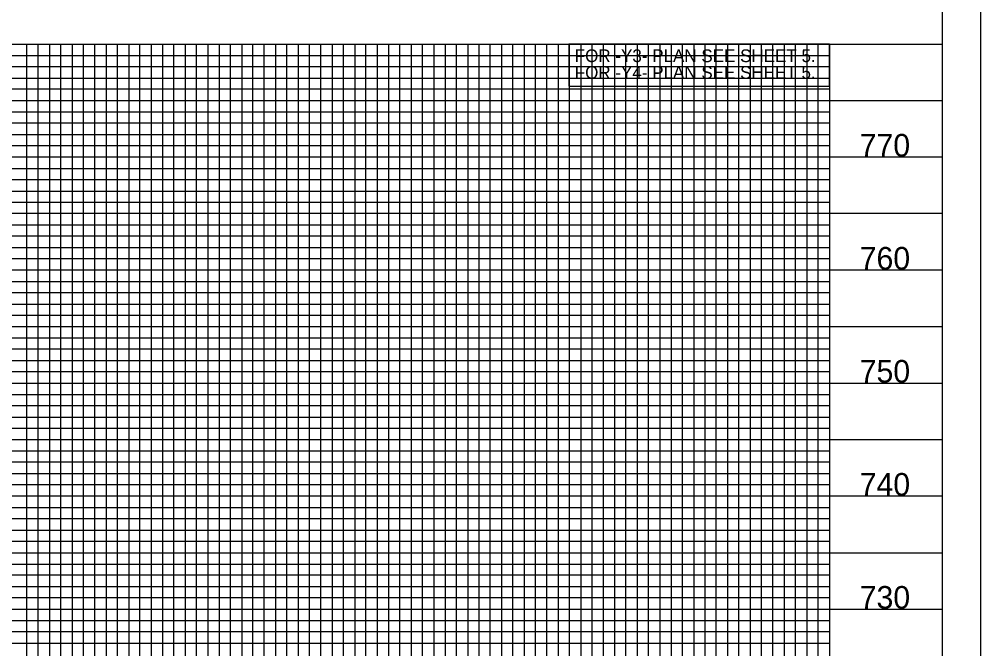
# Model space of a CAD drawing. Extents: x 1524869 to 1526553, y 501099 to 502199.
# Drawn here: x 1526127.7 to 1526553.1, y 501381.1 to 501659.6 of the extents above; entities that cross this region are included whole.
import ezdxf

# ---------------------------------------------------------------- set-up
doc = ezdxf.new("R2010")
doc.units = 0
for name, color, linetype in [('Exist Vertical Profile Vertical Axis Label', 7, 'Continuous'), ('Prop Grid Mask', 7, 'Continuous'), ('Prop Horizontal Alignment Curve and Spiral Data', 7, 'Continuous'), ('Sheet DOT Grid CELL', 7, 'Continuous'), ('Sheet Layout Profile Border Port 2', 7, 'Continuous'), ('Sheet Plot Border Outside CELL', 7, 'Continuous'), ('Sheet Profile CELL', 7, 'Continuous'), ('Sheet Profile Grid Major CELL', 7, 'Continuous'), ('Sheet Profile Grid Middle CELL', 7, 'Continuous'), ('Sheet Profile Grid Minor CELL', 7, 'Continuous')]:
    doc.layers.add(name, color=color, linetype=linetype)

msp = doc.modelspace()

# ---------------------------------------------------------------- linework, layer by layer
at = {"layer": 'Prop Grid Mask'}
msp.add_lwpolyline([(1526370.88, 501629.99), (1526486.08, 501629.99), (1526486.08, 501648.56), (1526370.88, 501648.56)], close=True, dxfattribs=at)
at = {"layer": 'Sheet DOT Grid CELL'}
msp.add_line((1525036.08, 501648.56), (1526535.97, 501648.56), dxfattribs=at)
at = {"layer": 'Sheet Layout Profile Border Port 2'}
msp.add_lwpolyline([(1525086.08, 501648.56), (1526486.08, 501648.56), (1526486.08, 501148.56), (1525086.08, 501148.56)], close=True, dxfattribs=at)
at = {"layer": 'Sheet Plot Border Outside CELL'}
msp.add_lwpolyline([(1524869.08, 501098.56), (1526553.08, 501098.56), (1526553.08, 502198.56), (1524869.08, 502198.56)], close=True, dxfattribs=at)
at = {"layer": 'Sheet Profile CELL'}
msp.add_line((1525036.08, 501648.56), (1526536.08, 501648.56), dxfattribs=at)
msp.add_lwpolyline([(1526536.08, 502173.56), (1525036.08, 502173.56), (1525036.08, 501123.56), (1526536.08, 501123.56)], close=True, dxfattribs=at)
at = {"layer": 'Sheet Profile Grid Major CELL'}
for p, q in [((1526136.08, 501648.56), (1526186.08, 501648.56)), ((1526236.08, 501648.56), (1526286.08, 501648.56)), ((1526336.08, 501648.56), (1526386.08, 501648.56)), ((1526436.08, 501648.56), (1526486.08, 501648.56))]:
    msp.add_line(p, q, dxfattribs=at)
for points in [[(1526086.08, 501148.56), (1526136.08, 501148.56), (1526136.08, 501648.56), (1526186.08, 501648.56), (1526186.08, 501148.56), (1526236.08, 501148.56), (1526236.08, 501648.56), (1526286.08, 501648.56), (1526286.08, 501148.56), (1526336.08, 501148.56), (1526336.08, 501648.56), (1526386.08, 501648.56), (1526386.08, 501148.56), (1526436.08, 501148.56), (1526436.08, 501148.56), (1526436.08, 501648.56), (1526486.08, 501648.56), (1526486.08, 501148.56)], [(1526536.08, 501598.56), (1525036.08, 501598.56)], [(1526536.08, 501548.56), (1525036.08, 501548.56), (1525036.08, 501498.56), (1526536.08, 501498.56)], [(1526536.08, 501448.56), (1525036.08, 501448.56), (1525036.08, 501398.56), (1526536.08, 501398.56)]]:
    msp.add_lwpolyline(points, dxfattribs=at)
at = {"layer": 'Sheet Profile Grid Middle CELL'}
for points in [[(1526111.08, 501148.56), (1526161.08, 501148.56), (1526161.08, 501648.56), (1526211.08, 501648.56), (1526211.08, 501148.56), (1526261.08, 501148.56), (1526261.08, 501648.56), (1526311.08, 501648.56), (1526311.08, 501148.56), (1526361.08, 501148.56), (1526361.08, 501648.56), (1526411.08, 501648.56), (1526411.08, 501148.56), (1526461.08, 501148.56), (1526461.08, 501648.56)], [(1525036.08, 501623.56), (1526536.08, 501623.56)], [(1526536.08, 501573.56), (1525036.08, 501573.56), (1525036.08, 501523.56), (1526536.08, 501523.56)], [(1526536.08, 501473.56), (1525036.08, 501473.56), (1525036.08, 501423.56), (1526536.08, 501423.56)]]:
    msp.add_lwpolyline(points, dxfattribs=at)
at = {"layer": 'Sheet Profile Grid Minor CELL'}
for p, q in [((1525086.08, 501643.56), (1526486.08, 501643.56)), ((1526486.08, 501638.56), (1525086.08, 501638.56)), ((1525086.08, 501633.56), (1526486.08, 501633.56)), ((1526486.08, 501628.56), (1525086.08, 501628.56)), ((1525086.08, 501618.56), (1526486.08, 501618.56)), ((1526486.08, 501613.56), (1525086.08, 501613.56)), ((1525086.08, 501608.56), (1526486.08, 501608.56)), ((1526486.08, 501603.56), (1525086.08, 501603.56)), ((1525086.08, 501593.56), (1526486.08, 501593.56)), ((1526486.08, 501588.56), (1525086.08, 501588.56)), ((1525086.08, 501583.56), (1526486.08, 501583.56)), ((1526486.08, 501578.56), (1525086.08, 501578.56)), ((1525086.08, 501568.56), (1526486.08, 501568.56)), ((1526486.08, 501563.56), (1525086.08, 501563.56)), ((1525086.08, 501558.56), (1526486.08, 501558.56)), ((1526486.08, 501553.56), (1525086.08, 501553.56)), ((1525086.08, 501543.56), (1526486.08, 501543.56)), ((1526486.08, 501538.56), (1525086.08, 501538.56)), ((1525086.08, 501533.56), (1526486.08, 501533.56)), ((1526486.08, 501528.56), (1525086.08, 501528.56)), ((1525086.08, 501518.56), (1526486.08, 501518.56)), ((1526486.08, 501513.56), (1525086.08, 501513.56)), ((1525086.08, 501508.56), (1526486.08, 501508.56)), ((1526486.08, 501503.56), (1525086.08, 501503.56)), ((1525086.08, 501493.56), (1526486.08, 501493.56)), ((1526486.08, 501488.56), (1525086.08, 501488.56)), ((1525086.08, 501483.56), (1526486.08, 501483.56)), ((1526486.08, 501478.56), (1525086.08, 501478.56)), ((1525086.08, 501468.56), (1526486.08, 501468.56)), ((1526486.08, 501463.56), (1525086.08, 501463.56)), ((1525086.08, 501458.56), (1526486.08, 501458.56)), ((1526486.08, 501453.56), (1525086.08, 501453.71)), ((1525086.08, 501443.56), (1526486.08, 501443.56)), ((1526486.08, 501438.56), (1525086.08, 501438.56)), ((1525086.08, 501433.56), (1526486.08, 501433.56)), ((1526486.08, 501428.56), (1525086.08, 501428.56)), ((1525086.08, 501418.56), (1526486.08, 501418.56)), ((1526486.08, 501413.56), (1525086.08, 501413.56)), ((1525086.08, 501408.56), (1526486.08, 501408.56)), ((1526486.08, 501403.56), (1525086.08, 501403.56)), ((1525086.08, 501393.56), (1526486.08, 501393.56)), ((1526486.08, 501388.56), (1525086.08, 501388.56)), ((1525086.08, 501383.56), (1526486.08, 501383.56))]:
    msp.add_line(p, q, dxfattribs=at)
for points in [[(1526131.08, 501148.56), (1526131.08, 501648.56), (1526141.08, 501648.56), (1526141.08, 501148.56)], [(1526146.08, 501148.56), (1526146.08, 501648.56), (1526151.08, 501648.56), (1526151.08, 501148.56)], [(1526156.08, 501148.56), (1526156.08, 501648.56), (1526166.08, 501648.56), (1526166.08, 501148.56)], [(1526171.08, 501148.56), (1526171.08, 501648.56), (1526176.08, 501648.56), (1526176.08, 501148.56)], [(1526181.08, 501148.56), (1526181.08, 501648.56), (1526191.08, 501648.56), (1526191.08, 501148.56)], [(1526196.08, 501148.56), (1526196.08, 501648.56), (1526201.08, 501648.56), (1526201.08, 501148.56)], [(1526206.08, 501148.56), (1526206.08, 501648.56), (1526216.08, 501648.56), (1526216.08, 501148.56)], [(1526221.08, 501148.56), (1526221.08, 501648.56), (1526226.08, 501648.56), (1526226.08, 501148.56)], [(1526231.08, 501148.56), (1526231.08, 501648.56), (1526241.08, 501648.56), (1526241.08, 501148.56)], [(1526246.08, 501148.56), (1526246.08, 501648.56), (1526251.08, 501648.56), (1526251.08, 501148.56)], [(1526256.08, 501148.56), (1526256.08, 501648.56), (1526266.08, 501648.56), (1526266.08, 501148.56)], [(1526271.08, 501148.56), (1526271.08, 501648.56), (1526276.08, 501648.56), (1526276.08, 501148.56)], [(1526281.08, 501148.56), (1526281.08, 501648.56), (1526291.08, 501648.56), (1526291.08, 501148.56)], [(1526296.08, 501148.56), (1526296.08, 501648.56), (1526301.08, 501648.56), (1526301.08, 501148.56)], [(1526306.08, 501148.56), (1526306.08, 501648.56), (1526316.08, 501648.56), (1526316.08, 501148.56)], [(1526321.08, 501148.56), (1526321.08, 501648.56), (1526326.08, 501648.56), (1526326.08, 501148.56)], [(1526331.08, 501148.56), (1526331.08, 501648.56), (1526341.08, 501648.56), (1526341.08, 501148.56)], [(1526346.08, 501148.56), (1526346.08, 501648.56), (1526351.08, 501648.56), (1526351.08, 501148.56)], [(1526356.08, 501148.56), (1526356.08, 501648.56), (1526366.08, 501648.56), (1526366.08, 501148.56)], [(1526371.08, 501148.56), (1526371.08, 501648.56), (1526376.08, 501648.56), (1526376.08, 501148.56)], [(1526381.08, 501148.56), (1526381.08, 501648.56), (1526391.08, 501648.56), (1526391.08, 501148.56)], [(1526396.08, 501148.56), (1526396.08, 501648.56), (1526401.08, 501648.56), (1526401.08, 501148.56)], [(1526406.08, 501148.56), (1526406.08, 501648.56), (1526416.08, 501648.56), (1526416.08, 501148.56)], [(1526421.08, 501148.56), (1526421.08, 501648.56), (1526426.08, 501648.56), (1526426.08, 501148.56)], [(1526431.08, 501148.56), (1526431.08, 501648.56), (1526441.08, 501648.56), (1526441.08, 501148.56)], [(1526446.08, 501148.56), (1526446.08, 501648.56), (1526451.08, 501648.56), (1526451.08, 501148.56)], [(1526456.08, 501148.56), (1526456.08, 501648.56), (1526466.08, 501648.56), (1526466.08, 501148.56)], [(1526471.08, 501148.56), (1526471.08, 501648.56), (1526476.08, 501648.56), (1526476.08, 501148.56)], [(1526481.08, 501148.56), (1526481.08, 501648.56), (1526486.08, 501648.56)]]:
    msp.add_lwpolyline(points, dxfattribs=at)

# ---------------------------------------------------------------- texts
at = {"layer": 'Exist Vertical Profile Vertical Axis Label'}
for s, p in [('770', (1526499.51, 501598.81)), ('760', (1526499.51, 501548.81)), ('750', (1526499.51, 501498.81)), ('740', (1526499.51, 501448.81)), ('730', (1526499.51, 501398.81))]:
    msp.add_text(s, height=10, dxfattribs=at).set_placement(p)
at = {"layer": 'Prop Horizontal Alignment Curve and Spiral Data'}
for s, p in [('FOR -Y3- PLAN SEE SHEET 5.', (1526373.44, 501640.59)), ('FOR -Y4- PLAN SEE SHEET 5.', (1526373.44, 501633.21))]:
    msp.add_text(s, height=5.625, rotation=360, dxfattribs=at).set_placement(p)

doc.saveas('drawing.dxf')
